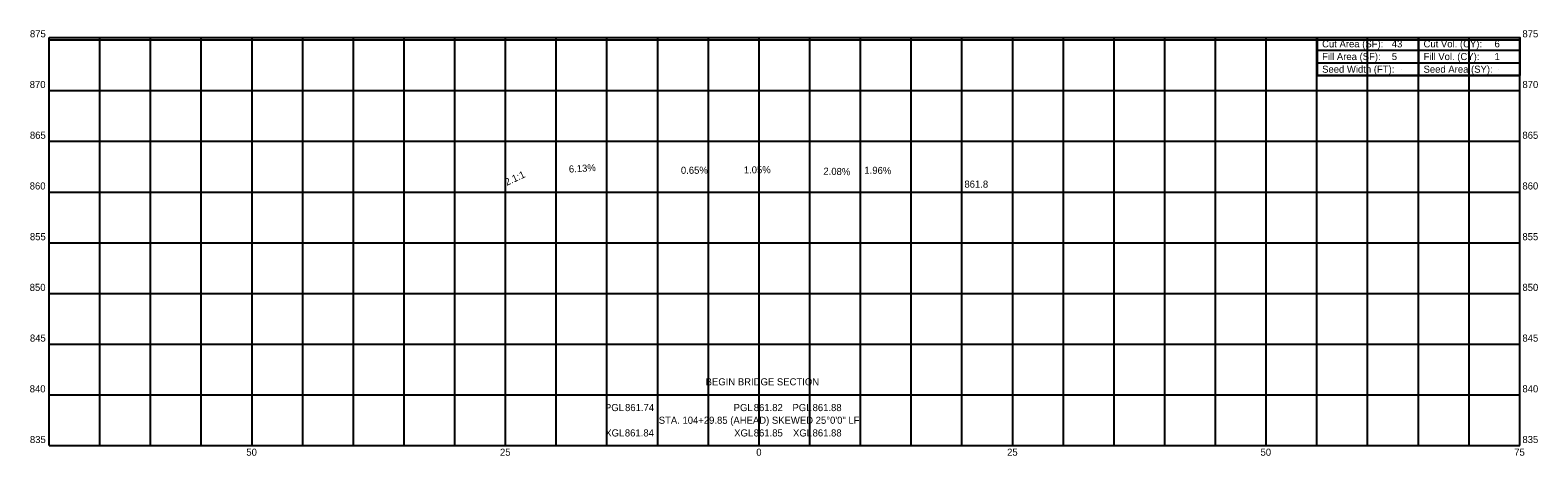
# Model space of a CAD drawing. Extents: x -72 to 77, y 834 to 876.
import ezdxf

# ---------------------------------------------------------------- set-up
doc = ezdxf.new("R2010")
doc.units = 0
for name, color, linetype in [('-BNDY_Scratch', 7, 'Continuous'), ('Default', 7, 'Continuous'), ('RW_X_Esmt_General', 7, 'Continuous'), ('RW_X_Text', 7, 'Continuous'), ('SC_Scratch1', 7, 'Continuous')]:
    doc.layers.add(name, color=color, linetype=linetype)

msp = doc.modelspace()

# ---------------------------------------------------------------- linework, layer by layer
at = {"layer": '-BNDY_Scratch'}
msp.add_lwpolyline([(55.01, 875.23), (75.01, 875.23), (75.01, 871.48), (55.01, 871.48)], close=True, dxfattribs=at)
msp.add_lwpolyline([(55.01, 875.23), (75.01, 875.23), (75.01, 871.48), (55.01, 871.48)], close=True, dxfattribs=at)
msp.add_lwpolyline([(55.01, 875.23), (75.01, 875.23), (75.01, 871.48), (55.01, 871.48)], close=True, dxfattribs=at)
at = {"layer": 'Default'}
msp.add_circle((75.01, 875.23), 0.000417, dxfattribs=at)
msp.add_circle((75.01, 875.23), 0.000417, dxfattribs=at)
msp.add_circle((75.01, 875.23), 0.000417, dxfattribs=at)
msp.add_circle((75.01, 875.23), 0.000417, dxfattribs=at)
msp.add_circle((75.01, 875.23), 0.000417, dxfattribs=at)
msp.add_circle((75.01, 875.23), 0.000417, dxfattribs=at)
msp.add_circle((75.01, 875.23), 0.000417, dxfattribs=at)
msp.add_circle((75.01, 875.23), 0.000417, dxfattribs=at)
msp.add_circle((75.01, 875.23), 0.000417, dxfattribs=at)
msp.add_circle((75.01, 875.23), 0.000417, dxfattribs=at)
msp.add_circle((75.01, 875.23), 0.000417, dxfattribs=at)
msp.add_circle((75.01, 875.23), 0.000417, dxfattribs=at)
msp.add_circle((75.01, 875.23), 0.000417, dxfattribs=at)
msp.add_circle((75.01, 875.23), 0.000417, dxfattribs=at)
msp.add_circle((75.01, 875.23), 0.000417, dxfattribs=at)
msp.add_circle((75.01, 875.23), 0.000417, dxfattribs=at)
msp.add_circle((75.01, 875.23), 0.000417, dxfattribs=at)
msp.add_circle((75.01, 875.23), 0.000417, dxfattribs=at)
msp.add_circle((75.01, 875.23), 0.000417, dxfattribs=at)
msp.add_circle((75.01, 875.23), 0.000417, dxfattribs=at)
msp.add_circle((75.01, 875.23), 0.000417, dxfattribs=at)
msp.add_circle((75.01, 875.23), 0.000417, dxfattribs=at)
msp.add_circle((75.01, 875.23), 0.000417, dxfattribs=at)
msp.add_circle((75.01, 875.23), 0.000417, dxfattribs=at)
msp.add_circle((75.01, 875.23), 0.000417, dxfattribs=at)
msp.add_circle((75.01, 875.23), 0.000417, dxfattribs=at)
msp.add_circle((75.01, 875.23), 0.000417, dxfattribs=at)
msp.add_circle((75.01, 875.23), 0.000417, dxfattribs=at)
msp.add_circle((75.01, 875.23), 0.000417, dxfattribs=at)
msp.add_circle((75.01, 875.23), 0.000417, dxfattribs=at)
msp.add_circle((75.01, 875.23), 0.000417, dxfattribs=at)
msp.add_circle((75.01, 875.23), 0.000417, dxfattribs=at)
msp.add_circle((75.01, 875.23), 0.000417, dxfattribs=at)
msp.add_circle((75.01, 875.23), 0.000417, dxfattribs=at)
msp.add_circle((75.01, 875.23), 0.000417, dxfattribs=at)
msp.add_circle((75.01, 875.23), 0.000417, dxfattribs=at)
at = {"layer": 'RW_X_Esmt_General'}
for p, q in [((55.01, 875.23), (75.01, 875.23)), ((55.01, 875.23), (55.01, 872.73)), ((55.01, 875.23), (75.01, 875.23)), ((55.01, 875.23), (55.01, 872.73)), ((55.01, 875.23), (75.01, 875.23)), ((55.01, 875.23), (55.01, 872.73)), ((65.01, 875.23), (65.01, 871.48)), ((65.01, 875.23), (65.01, 871.48)), ((65.01, 875.23), (65.01, 871.48)), ((75.01, 875.23), (75.01, 872.73)), ((75.01, 875.23), (75.01, 872.73)), ((75.01, 875.23), (75.01, 872.73)), ((55.01, 873.98), (75.01, 873.98)), ((55.01, 873.98), (75.01, 873.98)), ((55.01, 873.98), (75.01, 873.98)), ((55.01, 872.73), (75.01, 872.73)), ((55.01, 872.73), (75.01, 872.73)), ((55.01, 872.73), (75.01, 872.73)), ((63.3, 872.11), (63.3, 872.11)), ((63.3, 872.11), (63.3, 872.11)), ((63.3, 872.11), (63.3, 872.11)), ((72.95, 872.11), (72.95, 872.11)), ((72.95, 872.11), (72.95, 872.11)), ((72.95, 872.11), (72.95, 872.11))]:
    msp.add_line(p, q, dxfattribs=at)
msp.add_lwpolyline([(55.01, 872.73), (55.01, 871.48), (75.01, 871.48), (75.01, 872.73)], dxfattribs=at)
msp.add_lwpolyline([(55.01, 872.73), (55.01, 871.48), (75.01, 871.48), (75.01, 872.73)], dxfattribs=at)
msp.add_lwpolyline([(55.01, 872.73), (55.01, 871.48), (75.01, 871.48), (75.01, 872.73)], dxfattribs=at)
at = {"layer": 'SC_Scratch1'}
for p, q in [((-69.99, 875.23), (75.01, 875.23)), ((-69.99, 835), (-69.99, 875.23)), ((-69.99, 875), (75.01, 875)), ((-65, 835), (-65, 875.23)), ((-60, 835), (-60, 875.23)), ((-55, 835), (-55, 875.23)), ((-50, 835), (-50, 875.23)), ((-45, 835), (-45, 875.23)), ((-40, 835), (-40, 875.23)), ((-35, 835), (-35, 875.23)), ((-30, 835), (-30, 875.23)), ((-25, 835), (-25, 875.23)), ((-20, 835), (-20, 875.23)), ((-15, 835), (-15, 875.23)), ((-10, 835), (-10, 875.23)), ((-5, 835), (-5, 875.23)), ((0, 835), (0, 875.23)), ((5, 835), (5, 875.23)), ((10, 835), (10, 875.23)), ((15, 835), (15, 875.23)), ((20, 835), (20, 875.23)), ((25, 835), (25, 875.23)), ((30, 835), (30, 875.23)), ((35, 835), (35, 875.23)), ((40, 835), (40, 875.23)), ((45, 835), (45, 875.23)), ((50, 835), (50, 875.23)), ((55, 835), (55, 875.23)), ((60, 835), (60, 875.23)), ((65, 835), (65, 875.23)), ((70, 835), (70, 875.23)), ((75, 835), (75, 875.23)), ((75.01, 835), (75.01, 875.23)), ((-69.99, 870), (75.01, 870)), ((-69.99, 865), (75.01, 865)), ((-69.99, 860), (75.01, 860)), ((-69.99, 855), (75.01, 855)), ((-69.99, 850), (75.01, 850)), ((-69.99, 845), (75.01, 845)), ((-69.99, 840), (75.01, 840)), ((-69.99, 835), (75.01, 835))]:
    msp.add_line(p, q, dxfattribs=at)

# ---------------------------------------------------------------- texts
at = {"layer": 'RW_X_Text'}
for s, p in [('875', (-71.9, 875.25)), ('875', (75.26, 875.25)), ('Cut Area (SF):', (55.51, 874.26)), ('Cut Area (SF):', (55.51, 874.26)), ('Cut Area (SF):', (55.51, 874.26)), ('43', (62.38, 874.26)), ('43', (62.38, 874.26)), ('43', (62.38, 874.26)), ('Cut Vol. (CY):', (65.51, 874.26)), ('Cut Vol. (CY):', (65.51, 874.26)), ('Cut Vol. (CY):', (65.51, 874.26)), ('6', (72.51, 874.26)), ('6', (72.51, 874.26)), ('6', (72.51, 874.26)), ('Fill Area (SF):', (55.51, 873.01)), ('Fill Area (SF):', (55.51, 873.01)), ('Fill Area (SF):', (55.51, 873.01)), ('5', (62.38, 873.01)), ('5', (62.38, 873.01)), ('5', (62.38, 873.01)), ('Fill Vol. (CY):', (65.51, 873.01)), ('Fill Vol. (CY):', (65.51, 873.01)), ('Fill Vol. (CY):', (65.51, 873.01)), ('1', (72.51, 873.01)), ('1', (72.51, 873.01)), ('1', (72.51, 873.01)), ('Seed Width (FT):', (55.51, 871.76)), ('Seed Width (FT):', (55.51, 871.76)), ('Seed Width (FT):', (55.51, 871.76)), ('Seed Area (SY):', (65.51, 871.76)), ('Seed Area (SY):', (65.51, 871.76)), ('Seed Area (SY):', (65.51, 871.76)), ('870', (-71.92, 870.25)), ('870', (75.26, 870.25)), ('865', (-71.9, 865.25)), ('865', (75.26, 865.25)), ('860', (-71.92, 860.25)), ('861.8', (20.24, 860.43)), ('860', (75.26, 860.25)), ('855', (-71.9, 855.25)), ('855', (75.26, 855.25)), ('850', (-71.92, 850.25)), ('850', (75.26, 850.25)), ('845', (-71.9, 845.25)), ('845', (75.26, 845.25)), ('BEGIN BRIDGE SECTION', (-5.27, 840.94)), ('840', (-71.92, 840.25)), ('840', (75.26, 840.25)), ('PGL ', (-15.2, 838.4)), ('861.74', (-13.22, 838.4)), ('PGL ', (-2.51, 838.4)), ('861.82', (-0.53, 838.4)), ('PGL ', (3.29, 838.4)), ('861.88', (5.27, 838.4)), ('STA. 104+29.85 (AHEAD) SKEWED 25°0\'0" LF', (-9.9, 837.15)), ('835', (-71.9, 835.25)), ('XGL ', (-15.17, 835.9)), ('861.84', (-13.24, 835.9)), ('XGL ', (-2.46, 835.9)), ('861.85', (-0.53, 835.9)), ('XGL ', (3.34, 835.9)), ('861.88', (5.27, 835.9)), ('835', (75.26, 835.25)), ('50', (-50.56, 834)), ('25', (-25.55, 834)), ('0', (-0.28, 834)), ('25', (24.45, 834)), ('50', (49.44, 834)), ('75', (74.45, 834))]:
    msp.add_text(s, height=0.7, dxfattribs=at).set_placement(p)
for s, rotation, p in [('6.13%', 3.5096, (-18.74, 861.91)), ('0.65%', 0.3712, (-7.71, 861.79)), ('1.05%', 0.6007, (-1.51, 861.83)), ('2.08%', 358.8109, (6.33, 861.71)), ('1.96%', 358.8796, (10.37, 861.81)), ('2.1:1', 25.2341, (-24.88, 860.6))]:
    msp.add_text(s, height=0.7, rotation=rotation, dxfattribs=at).set_placement(p)

doc.saveas('drawing.dxf')
